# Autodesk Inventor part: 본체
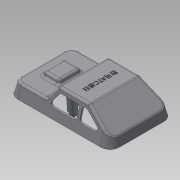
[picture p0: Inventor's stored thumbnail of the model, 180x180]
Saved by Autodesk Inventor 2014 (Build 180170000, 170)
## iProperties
Created: 2015-05
Part Number: 본체
Material: Generic
Document SubType Name: Modeling
Designer: Administrator
Density: 1 g/cm^3
Appearance: Default
Author: Administrator
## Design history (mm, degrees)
sketch "스케치1"
  geometry: L1 (-49, -38)-(49, -38); L2 (61, -26)-(61, 26); L3 (49, 38)-(-49, 38); L4 (-61, 26)-(-61, -26); L5 (-61, -38)-(61, 38); L6 (61, -38)-(-61, 38); A1 r 12 centre (-49, 26) between (-49, 38) and (-61, 26); A2 r 12 centre (-49, -26) between (-61, -26) and (-49, -38); A3 r 12 centre (49, -26) between (49, -38) and (61, -26); A4 r 12 centre (49, 26) between (61, 26) and (49, 38); 1 further point
  constraints: 12 end point, 8 point on circle, 8 point on line, 8 tangent, 4 centre point, 3 equal radius, 2 midpoint, 2 parallel, 1 horizontal, 1 perpendicular
  dimensions: "d0" = 122 distance of L5.end L6.end; "d1" = 76 distance of L6.start L5.end; "d2" = 12 radius of A1
extrude "돌출1" new body sketch "스케치1" distance "d3" = 30; taper "d4" = -15 deg
sketch "스케치2"
  geometry: L1 (-28.321, 30)-(-58.321, 30); L2 (-58.321, 30)-(-58.321, 10); L3 (-58.321, 10)-(-28.321, 30); L4 (49, 30)-(-49, 30) reference; L5 (-61, 0)-(-52.962, 30) reference; L6 (49, 0)-(-49, 0) reference; 1 further point
  constraints: 6 end point, 1 horizontal, 1 perpendicular, 1 point on line
  dimensions: "d6" = 30 distance of L1.start L1.end; "d11" = 30 distance between parallel lines of L6 L1; "d12" = 20 distance of L1.end L2.end
extrude "돌출2" cut sketch "스케치2" stored distance "d13" = 30; taper "d14" = 0 deg
sketch "스케치3"
  geometry: L1 (49, 0)-(-49, 0) reference; L2 (49, 0)-(61, 0) reference; L3 (49, 30)-(-28.321, 30) reference; L4 (19, 14.382)-(34.522, 14.382); L5 (34.522, 14.382)-(61, 14.382); L6 (61, 0)-(52.962, 30) reference; L7 (19, 14.382)-(8.064, 30); L8 (8.064, 30)-(52.962, 30); L9 (57.146, 14.382)-(52.962, 30); 1 further point
  constraints: 10 end point, 3 point on line, 2 collinear, 2 parallel
  dimensions: "d17" = 42 horizontal distance of L4.start L2.end; "d20" = 125 deg angle of L7 L4
extrude "돌출3" cut sketch "스케치3" stored distance "d21" = 30; taper "d22" = 0 deg
sketch "스케치4"
  geometry: L1 (4.527, 47.146)-(24.527, 47.146); L2 (24.527, 47.146)-(24.527, 21.146); L3 (24.527, 21.146)-(4.527, 21.146); L4 (4.527, 21.146)-(4.527, 47.146); L5 (-12, 8.146)-(-12, 60.146) reference; L6 (98, -3.854)-(0, -3.854) reference; 3 further points
  constraints: 8 end point, 2 midpoint, 2 parallel, 1 horizontal, 1 horizontal alignment, 1 perpendicular
  dimensions: "d23" = 20 distance of L1.start L1.end; "d26" = 26 distance of L1.end L2.end; "d27" = 38 distance from line of L6 point (4.527, 34.146) (derived)
extrude "돌출4" join sketch "스케치4" distance "d28" = 5; taper "d29" = 0 deg
fillet "모깎기1" dims "d30" = 3
fillet "모깎기2" dims "d31" = 3
fillet "모깎기3" dims "d32" = 3
feature "쉘2" dims "d34" = 2
sketch "스케치5"
  geometry: L1 (6.502, 30)-(-27.412, 30) reference; L2 (-29.076, 29.496)-(-50.664, 15.104) reference; L3 (18.104, 15.661)-(8.96, 28.721) reference; L4 (12.659, 14.721)-(6.357, 23.721); L5 (3.899, 25)-(-15.036, 25); L6 (10.201, 10)-(-15.036, 10); L7 (-18.036, 13)-(-18.036, 22); A1 r 3 centre (10.201, 13) between (10.201, 10) and (12.659, 14.721); A2 r 3 centre (3.899, 22) between (6.357, 23.721) and (3.899, 25); A3 r 3 centre (-15.036, 22) between (-15.036, 25) and (-18.036, 22); A4 r 3 centre (-15.036, 13) between (-18.036, 13) and (-15.036, 10); 4 further points
  constraints: 8 end point, 8 point on circle, 8 tangent, 6 point on line, 4 centre point, 3 equal radius, 3 parallel, 1 perpendicular
  dimensions: "d35" = 5 distance between parallel lines of L4 L3; "d36" = 5 distance between parallel lines of L1 L5; "d37" = 34 distance of point (15.964, 10) point (-18.036, 10); "d38" = 15 distance of point (-18.036, 10) point (-18.036, 25); "d39" = 3 radius of A1
extrude "돌출5" cut sketch "스케치5" stored distance "d40" = 5; taper "d41" = 0 deg
sketch "스케치6"
  geometry: L1 (-50.664, 15.104)-(-29.076, 29.496) reference; L2 (-27.412, 30)-(6.502, 30) reference; L3 (49, 0)-(-49, 0) reference; L4 (-41.062, 15.496)-(-27.562, 24.496); L5 (-25.898, 25)-(-24.307, 25); L6 (-39.398, 10)-(-24.307, 10); L7 (-21.307, 13)-(-21.307, 22); A1 r 3 centre (-25.898, 22) between (-25.898, 25) and (-27.562, 24.496); A2 r 3 centre (-24.307, 22) between (-21.307, 22) and (-24.307, 25); A3 r 3 centre (-24.307, 13) between (-24.307, 10) and (-21.307, 13); A4 r 3 centre (-39.398, 13) between (-41.062, 15.496) and (-39.398, 10); 3 further points
  constraints: 8 end point, 8 point on circle, 8 tangent, 4 centre point, 4 point on line, 3 equal radius, 3 parallel, 1 perpendicular
  dimensions: "d42" = 5 distance between parallel lines of L1 L4; "d43" = 5 distance between parallel lines of L2 L5; "d45" = 28 distance of point (-49.307, 10) point (-21.307, 10); "d46" = 15 distance between parallel lines of L5 L6; "d47" = 3 radius of A1
extrude "돌출6" cut sketch "스케치6" stored distance "d48" = 5; taper "d49" = 0 deg
sketch "스케치7"
  geometry: L1 (58.929, 26)-(58.929, -26) reference; L2 (49, -35.929)-(-49, -35.929) reference; L3 (-58.929, -26)-(-58.929, 26) reference; L4 (-49, 35.929)-(49, 35.929) reference; L5 (59.929, 26)-(59.929, -26); L6 (49, -36.929)-(-49, -36.929); L7 (-59.929, -26)-(-59.929, 26); L8 (-49, 36.929)-(49, 36.929); A1 r 9.929 centre (49, 26) between (58.929, 26) and (49, 35.929) reference; A2 r 9.929 centre (49, -26) between (49, -35.929) and (58.929, -26) reference; A3 r 9.929 centre (-49, -26) between (-58.929, -26) and (-49, -35.929) reference; A4 r 9.929 centre (-49, 26) between (-49, 35.929) and (-58.929, 26) reference; A5 r 10.929 centre (49, 26) between (59.929, 26) and (49, 36.929); A6 r 10.929 centre (49, -26) between (49, -36.929) and (59.929, -26); A7 r 10.929 centre (-49, -26) between (-59.929, -26) and (-49, -36.929); A8 r 10.929 centre (-49, 26) between (-49, 36.929) and (-59.929, 26); 1 further point
  constraints: 8 end point, 8 point on circle, 4 centre point, 7 other
  dimensions: "d50" = 1 distance between parallel lines of L4 L8
extrude "돌출7" join sketch "스케치7" distance "d51" = 1; taper "d52" = 0 deg
node "작업 평면1"
sketch "스케치8"
  geometry: A1 r 4 centre (21, 0) between (25, 0) and (17, 0); A2 r 4 centre (10, 0) between (14, 0) and (6, 0); A3 r 4 centre (-10, 0) between (-6, 0) and (-14, 0); A4 r 4 centre (-21, 0) between (-17, 0) and (-25, 0); 3 further points
  constraints: 8 point on circle, 4 centre point, 2 horizontal alignment, 9 other
  dimensions: "d54" = 8 diameter of A4; "d55" = 8 diameter of A3; "d56" = 8 diameter of A2; "d57" = 8 diameter of A1; "d58" = 10 distance of A3.centre point (0, 0); "d59" = 20 distance of A3.centre A2.centre; "d60" = 11 distance of A2.centre A1.centre; "d61" = 11 distance of A4.centre A3.centre
extrude "돌출8" join sketch "스케치8" stored distance "d62" = 8 (= d57); taper "d63" = 0 deg
chamfer "모따기1" distance "d64" = 1; stored, may be unused: second distance "d65" = 2, angle "d66" = 45 deg
sketch "스케치9"
  geometry: L1 (-61, 26)-(-61, -26) reference; C1 r 3 at (-40, 0); 2 further points
  constraints: 1 centre point, 1 horizontal alignment, 1 midpoint
  dimensions: "d68" = 6 diameter of C1; "d69" = 21 distance from line of C1.centre L1
extrude "돌출9" join sketch "스케치9" stored distance "d71" = 8 (= d57); taper "d72" = 2.5 deg
sketch "스케치10"
  geometry: L1 (-26.487, 10)-(-26.487, -10) reference; L2 (-41.473, 10.986)-(-27.473, 10.986) reference; L3 (-42.459, -10)-(-42.459, 10) reference; L4 (-27.473, -10.986)-(-41.473, -10.986) reference; C1 r 3 at (-34.473, 0); 3 further points
  constraints: 2 midpoint, 1 centre point, 1 horizontal alignment, 1 vertical alignment
  dimensions: "d73" = 6 diameter of C1
extrude "돌출10" join sketch "스케치10" stored distance "d74" = 8 (= d57); taper "d75" = 2.5 deg
node "작업 평면2"
sketch "스케치13"
  geometry: C1 r 3 at (0, 22); C2 r 3 at (34.473, 0) reference; C3 r 3 at (-40, 0) reference; 1 further point
  constraints: 1 centre point
  dimensions: "d89" = 6 diameter of C1; "d91" = 22 vertical distance of C1.centre C3.centre; "d92" = 40 horizontal distance of C1.centre C3.centre
extrude "돌출13" join sketch "스케치13" stored distance "d93" = 8 (= d57); taper "d94" = 2.5 deg
node "작업 평면3"
sketch "스케치15"
  geometry: L1 (45, 1)-(35, 1); L2 (35, 1)-(35, -1); L3 (35, -1)-(45, -1); L4 (45, -1)-(45, 1); L5 (45, 1)-(35, -1); L6 (35, 1)-(45, -1); L7 (5, -21)-(-5, -21); L8 (-5, -21)-(-5, -23); L9 (-5, -23)-(5, -23); L10 (5, -23)-(5, -21); L11 (5, -21)-(-5, -23); L12 (-5, -21)-(5, -23); L13 (5, 23)-(-5, 23); L14 (-5, 23)-(-5, 21); L15 (-5, 21)-(5, 21); L16 (5, 21)-(5, 23); L17 (5, 23)-(-5, 21); L18 (-5, 23)-(5, 21); L19 (-29.473, 1)-(-39.473, 1); L20 (-39.473, 1)-(-39.473, -1); L21 (-39.473, -1)-(-29.473, -1); L22 (-29.473, -1)-(-29.473, 1); L23 (-29.473, 1)-(-39.473, -1); L24 (-39.473, 1)-(-29.473, -1); C1 r 3 at (40, 0) reference; C2 r 3 at (0, 22) reference; C3 r 3 at (0, -22) reference; C4 r 3 at (-34.473, 0) reference; 1 further point
  constraints: 48 end point, 8 midpoint, 8 parallel, 4 horizontal, 4 perpendicular
  dimensions: "d96" = 10 distance of L1.start L1.end; "d97" = 2 distance of L1.end L2.end; "d98" = 10 distance of L14.end L15.end; "d99" = 2 distance of L13.end L14.end; "d100" = 10 distance of L7.start L7.end; "d101" = 2 distance of L7.end L8.end; "d102" = 10 distance of L19.start L19.end; "d103" = 2 distance of L19.end L20.end
extrude "돌출14" join sketch "스케치15" stored distance "d104" = 8 (= d57); taper "d105" = 2 deg
sketch "스케치16"
  geometry: L1 (2.079, 0)-(2.616, -15.391) reference; L2 (-2.921, 0.035)-(-2.921, -15.337); L3 (-7.921, 0.07)-(-8.458, -15.284) reference; L4 (-7.921, 0.07)-(-10.647, -15.391); L5 (2.079, 0)-(4.793, -15.391); L6 (4.079, -14.121)-(-9.921, -14.121) reference; L7 (4.079, -16.987)-(-9.921, -16.987) reference; L8 (2.079, 0)-(2.572, -14.121); L9 (-7.921, 0.07)-(-8.417, -14.121); L10 (2.572, -14.121)-(2.616, -15.391); L11 (2.616, -15.391)-(4.793, -15.391); L12 (-8.417, -14.121)-(-8.462, -15.391); L13 (-8.462, -15.391)-(-10.647, -15.391); L14 (76.552, 0.07)-(77.046, -14.052) reference; L15 (66.552, 0.07)-(65.796, -21.538) reference; L16 (82.216, -11.962)-(60.628, -26.479) reference; L17 (71.552, 0.035)-(71.552, -19.133); L18 (76.552, 0.07)-(79.049, -14.091); L19 (71.552, -19.133)-(63.166, -19.133); L20 (71.552, -19.133)-(79.049, -14.091); L21 (66.552, 0.07)-(63.166, -19.133); L22 (65.88, -19.133)-(66.552, 0.07); L23 (76.552, 0.07)-(77.046, -14.052); L24 (77.046, -14.052)-(77.05, -14.161); L25 (77.048, -14.106)-(78.839, -12.902); 30 further points; 13 other entities
  constraints: 36 end point, 9 point on line, 6 collinear, 2 vertical, 1 midpoint, 1 parallel, 1 perpendicular, 21 other
  dimensions: "d106" = 10 deg angle of L5 L2; "d107" = 20 deg angle of L4 L5; "d110" = 10 deg angle of L18 L17; "d112" = 20 deg angle of L18 L21
  node "투영된 루프7"
  node "투영된 루프8"
extrude "돌출15" join sketch "스케치16" stored distance "d108" = 8 (= d57); taper "d109" = 0 deg
extrude "돌출16" join sketch "스케치16" stored distance "d113" = 8 (= d57); taper "d114" = 0 deg
sketch "스케치19"
  geometry: L1 (-26.016, -0.908)-(-26.016, 2.908) reference; L2 (0, 0)-(-26.016, -0.908) reference; L3 (0, 0)-(0, 2) reference; L4 (0, 2)-(-26.016, 2.908) reference; L5 (-25.603, 2.908)-(-25.603, -0.908) reference; L6 (0.349, 2)-(-25.603, 2.908) reference; L7 (0.349, 2)-(0.349, 0) reference; L8 (0.349, 0)-(-25.603, -0.908) reference; L9 (-25.81, 1)-(0.174, 1); L10 (0.349, 2)-(-26.217, 6.684); L11 (0.349, 0)-(-26.168, -4.676); L12 (-26.217, 50.66)-(-26.217, -4.66) reference; L13 (0.349, 0)-(-26.217, -0.929); L14 (0.349, 2)-(-26.217, 2.929); L15 (-26.217, 2.929)-(-26.217, 6.684); L16 (-25.583, -4.66)-(-25.583, 50.66) reference; L17 (-25.583, 6.572)-(-25.603, 2.908); L18 (-25.603, -0.908)-(-25.583, -4.572); 12 further points; 5 other entities
  constraints: 16 end point, 7 point on line, 3 collinear, 1 perpendicular, 9 other
  dimensions: "d119" = 10 deg angle of L10 L9; "d120" = 10 deg angle of L11 L9
  node "투영된 루프12"
  node "투영된 루프13"
sketch "스케치20"
  geometry: L1 (61, 26)-(61, -26) reference; 2 further points
  constraints: 1 horizontal alignment, 1 other
  dimensions: "d121" = 50 distance from line of point (11, 0) L1
feature "엠보싱1" sketch "스케치20" dims "d0" = 122, "d1" = 76, "d2" = 12, "d122" = 0.5, "d123" = 0
node "솔리드1"
mirror "대칭1"
node "투영된 루프3"
node "투영된 루프4"
node "투영된 루프5"
node "투영된 루프6"
other parameters: "d53" = -63, "d82" = 2, "d95" = 2, "d111" = 20 deg
